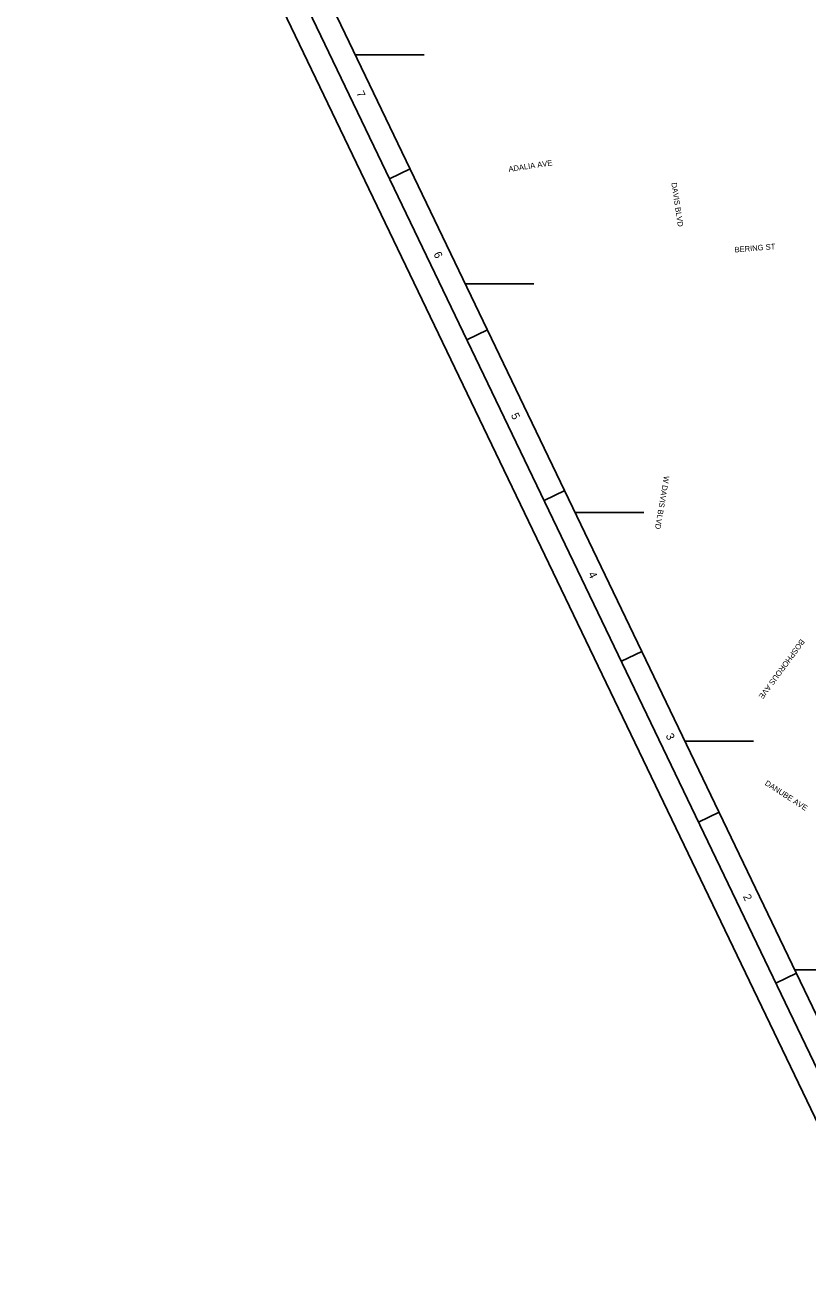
# Model space of a CAD drawing. Extents: x 507278 to 512248, y 1305805 to 1311243.
# Drawn here: x 507278 to 508988, y 1305805 to 1308565 of the extents above; entities that cross this region are included whole.
import ezdxf

# ---------------------------------------------------------------- set-up
doc = ezdxf.new("R2010")
doc.units = 0
for name, color, linetype in [('G-ANNO-NPLT', 7, 'Continuous'), ('G-ANNO-TTLB', 7, 'Continuous'), ('V-ROAD-IDEN', 7, 'Continuous'), ('V-TOPO-COOR-STAT', 7, 'Continuous')]:
    doc.layers.add(name, color=color, linetype=linetype)

msp = doc.modelspace()

# ---------------------------------------------------------------- linework, layer by layer
at = {"layer": 'G-ANNO-NPLT'}
msp.add_lwpolyline([(510343.2, 1311243.3), (512247.6, 1307276.8), (509182.6, 1305805.3), (507278.2, 1309771.7)], close=True, dxfattribs=at)
at = {"layer": 'G-ANNO-TTLB'}
for p, q in [((508074.2, 1308229.3), (508119.3, 1308251)), ((508243, 1307877.7), (508288.1, 1307899.4)), ((508411.8, 1307526.2), (508456.9, 1307547.8)), ((508580.6, 1307174.6), (508625.7, 1307196.2)), ((508749.4, 1306823), (508794.5, 1306844.7)), ((508918.2, 1306471.4), (508963.3, 1306493.1))]:
    msp.add_line(p, q, dxfattribs=at)
for points in [[(507344.9, 1309748.3), (509206, 1305872), (512180.9, 1307300.3), (510319.8, 1311176.6)], [(512114.2, 1307323.7), (510328.8, 1311042.3), (507444.1, 1309657.3), (509229.5, 1305938.7)]]:
    msp.add_lwpolyline(points, close=True, dxfattribs=at)
at = {"layer": 'V-TOPO-COOR-STAT'}
for p, q in [((508149.5, 1308500), (507999.7, 1308500)), ((508389.5, 1308000), (508239.8, 1308000)), ((508629.6, 1307500), (508479.8, 1307500)), ((508869.6, 1307000), (508719.9, 1307000)), ((509109.7, 1306500), (508960, 1306500))]:
    msp.add_line(p, q, dxfattribs=at)

# ---------------------------------------------------------------- texts
at = {"layer": 'G-ANNO-TTLB'}
for s, p in [('7', (508000.9, 1308416.7)), ('6', (508169.7, 1308065.1)), ('5', (508338.8, 1307712.8)), ('4', (508507.5, 1307365.4)), ('3', (508677, 1307012.2)), ('2', (508845.7, 1306660.8))]:
    msp.add_text(s, height=17.5, rotation=295.6468, dxfattribs=at).set_placement(p)
at = {"layer": 'V-ROAD-IDEN'}
for s, rotation, p in [('ADALIA AVE', 8.6314, (508334.9, 1308244.3)), ('DAVIS BLVD', 278.6314, (508689.8, 1308220.2)), ('BERING ST', 4.7981, (508828.4, 1308068.3)), ('W DAVIS BLVD', 260.3996, (508673.7, 1307580.6)), ('BOSPHOROUS AVE', 233.7114, (508972.6, 1307224.2)), ('DANUBE AVE', 327.1193, (508893, 1306905.2))]:
    msp.add_text(s, height=12, rotation=rotation, dxfattribs=at).set_placement(p)

doc.saveas('drawing.dxf')
